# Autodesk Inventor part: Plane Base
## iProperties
Author: Administrator
Created: 2001-01
Part Number: Plane Base
Document SubType Name: Modeling
Designer: Administrator
Control State: 0
Master: False
Checked Out: False
PropertySet Name: Design Tracking Control
Shininess: 0.0
PropertySet Name: _Private Model Information
Density: 0.0
Volumn: 0.0
Area: 0.0
PropertySet Name: Model Information
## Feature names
1. Extrusion1
2. Extrusion2
3. Extrusion4
4. Extrusion5
5. Chamfer1
6. Extrusion6
7. Extrusion7
8. Hole1
9. Hole2
10. Fillet1
11. Fillet2
